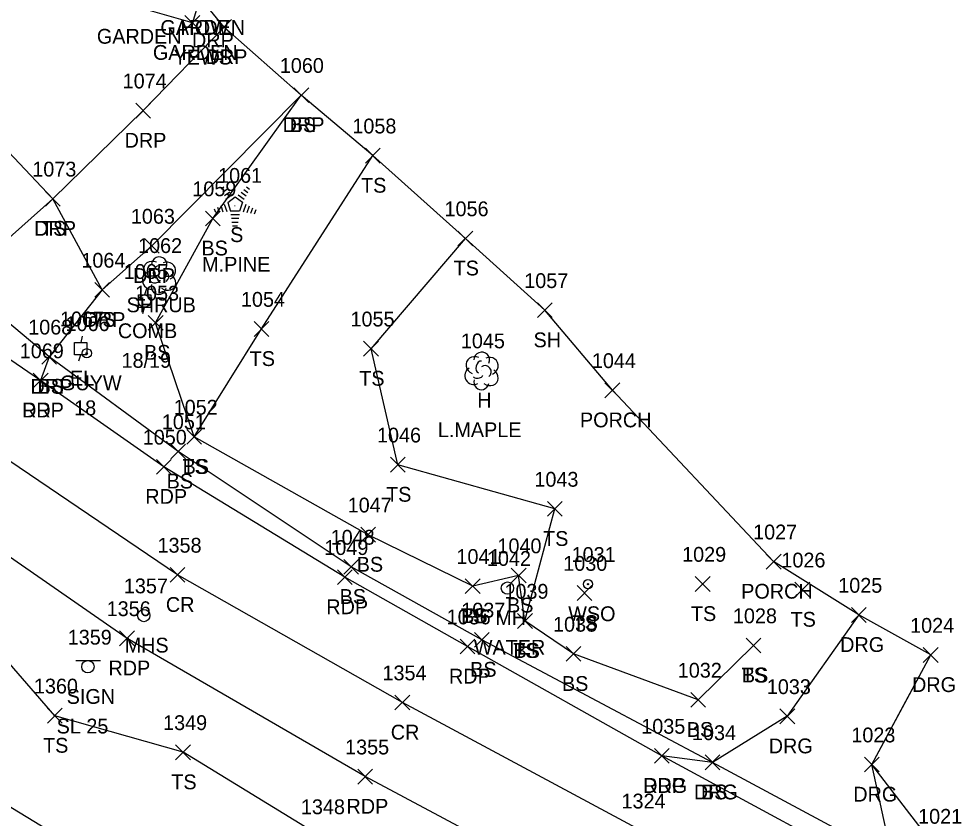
# Model space of a CAD drawing. Extents: x 1461855 to 1464118, y 556196 to 557441.
# Drawn here: x 1462535.4 to 1462662.7, y 556269.9 to 556377.9 of the extents above; entities that cross this region are included whole.
import ezdxf

# ---------------------------------------------------------------- set-up
doc = ezdxf.new("R2010")
doc.units = 0
for name, color, linetype in [('L_A', 7, 'Continuous'), ('L_C', 7, 'Continuous'), ('L_I', 7, 'Continuous'), ('L_TIC', 7, 'Continuous'), ('LAPB', 7, 'Continuous'), ('LBF', 7, 'Continuous'), ('LELB', 7, 'Continuous'), ('LSH', 7, 'Continuous'), ('LSOGP', 7, 'Continuous'), ('LTC', 7, 'Continuous'), ('LTD', 7, 'Continuous'), ('P_A', 7, 'Continuous'), ('P_I', 7, 'Continuous'), ('P_TIC', 7, 'Continuous'), ('PET', 7, 'Continuous'), ('PRC', 7, 'Continuous'), ('R_A', 7, 'Continuous'), ('R_I', 7, 'Continuous'), ('R_TIC', 7, 'Continuous'), ('RDG', 7, 'Continuous'), ('RDP', 7, 'Continuous'), ('S_A', 7, 'Continuous'), ('S_C', 7, 'Continuous'), ('S_I', 7, 'Continuous'), ('SSGN', 7, 'Continuous'), ('U_A', 7, 'Continuous'), ('U_C', 7, 'Continuous'), ('U_I', 7, 'Continuous'), ('UEPT', 7, 'Continuous'), ('UP', 7, 'Continuous'), ('UPGW', 7, 'Continuous'), ('USMH', 7, 'Continuous'), ('UUMH', 7, 'Continuous'), ('UWV', 7, 'Continuous')]:
    doc.layers.add(name, color=color, linetype=linetype)

msp = doc.modelspace()

# ---------------------------------------------------------------- linework, layer by layer
at = {"layer": 'L_TIC'}
for points in [[(1462557.88, 556376.35), (1462559.88, 556378.35)], [(1462559.88, 556376.35), (1462557.88, 556378.35)], [(1462572.59, 556366.59), (1462574.59, 556368.59)], [(1462574.59, 556366.59), (1462572.59, 556368.59)], [(1462582.26, 556358.41), (1462584.26, 556360.41)], [(1462584.26, 556358.41), (1462582.26, 556360.41)], [(1462539.02, 556352.59), (1462541.02, 556354.59)], [(1462541.02, 556352.59), (1462539.02, 556354.59)], [(1462560.65, 556349.93), (1462562.65, 556351.93)], [(1462562.65, 556349.93), (1462560.65, 556351.93)], [(1462594.76, 556347.23), (1462596.76, 556349.23)], [(1462596.76, 556347.23), (1462594.76, 556349.23)], [(1462545.7, 556340.28), (1462547.7, 556342.28)], [(1462547.7, 556340.28), (1462545.7, 556342.28)], [(1462605.48, 556337.53), (1462607.48, 556339.53)], [(1462607.48, 556337.53), (1462605.48, 556339.53)], [(1462552.91, 556335.84), (1462554.91, 556337.84)], [(1462554.91, 556335.84), (1462552.91, 556337.84)], [(1462567.21, 556335), (1462569.21, 556337)], [(1462569.21, 556335), (1462567.21, 556337)], [(1462582.01, 556332.34), (1462584.01, 556334.34)], [(1462584.01, 556332.34), (1462582.01, 556334.34)], [(1462538.52, 556331.25), (1462540.52, 556333.25)], [(1462540.52, 556331.25), (1462538.52, 556333.25)], [(1462614.62, 556326.72), (1462616.62, 556328.72)], [(1462616.62, 556326.72), (1462614.62, 556328.72)], [(1462558.12, 556320.43), (1462560.12, 556322.43)], [(1462560.12, 556320.43), (1462558.12, 556322.43)], [(1462558.12, 556320.43), (1462560.12, 556322.43)], [(1462560.12, 556320.43), (1462558.12, 556322.43)], [(1462555.96, 556318.46), (1462557.96, 556320.46)], [(1462557.96, 556318.46), (1462555.96, 556320.46)], [(1462585.64, 556316.67), (1462587.64, 556318.67)], [(1462587.64, 556316.67), (1462585.64, 556318.67)], [(1462606.85, 556310.7), (1462608.85, 556312.7)], [(1462608.85, 556310.7), (1462606.85, 556312.7)], [(1462581.63, 556307.22), (1462583.63, 556309.22)], [(1462583.63, 556307.22), (1462581.63, 556309.22)], [(1462579.33, 556302.87), (1462581.33, 556304.87)], [(1462581.33, 556302.87), (1462579.33, 556304.87)], [(1462636.4, 556303.58), (1462638.4, 556305.58)], [(1462638.4, 556303.58), (1462636.4, 556305.58)], [(1462601.95, 556301.71), (1462603.95, 556303.71)], [(1462603.95, 556301.71), (1462601.95, 556303.71)], [(1462595.75, 556300.27), (1462597.75, 556302.27)], [(1462597.75, 556300.27), (1462595.75, 556302.27)], [(1462595.75, 556300.27), (1462597.75, 556302.27)], [(1462597.75, 556300.27), (1462595.75, 556302.27)], [(1462626.82, 556300.56), (1462628.82, 556302.56)], [(1462628.82, 556300.56), (1462626.82, 556302.56)], [(1462610.84, 556299.34), (1462612.84, 556301.34)], [(1462612.84, 556299.34), (1462610.84, 556301.34)], [(1462640.28, 556299.79), (1462642.28, 556301.79)], [(1462642.28, 556299.79), (1462640.28, 556301.79)], [(1462602.81, 556295.57), (1462604.81, 556297.57)], [(1462604.81, 556295.57), (1462602.81, 556297.57)], [(1462602.81, 556295.57), (1462604.81, 556297.57)], [(1462604.81, 556295.57), (1462602.81, 556297.57)], [(1462596.97, 556293.03), (1462598.97, 556295.03)], [(1462598.97, 556293.03), (1462596.97, 556295.03)], [(1462633.67, 556292.26), (1462635.67, 556294.26)], [(1462635.67, 556292.26), (1462633.67, 556294.26)], [(1462633.67, 556292.26), (1462635.67, 556294.26)], [(1462635.67, 556292.26), (1462633.67, 556294.26)], [(1462609.37, 556291.12), (1462611.37, 556293.12)], [(1462611.37, 556291.12), (1462609.37, 556293.12)], [(1462626.22, 556284.91), (1462628.22, 556286.91)], [(1462628.22, 556284.91), (1462626.22, 556286.91)], [(1462539.3, 556282.77), (1462541.3, 556284.77)], [(1462541.3, 556282.77), (1462539.3, 556284.77)], [(1462556.62, 556277.83), (1462558.62, 556279.83)], [(1462558.62, 556277.83), (1462556.62, 556279.83)], [(1462628.14, 556276.47), (1462630.14, 556278.47)], [(1462630.14, 556276.47), (1462628.14, 556278.47)]]:
    msp.add_lwpolyline(points, dxfattribs=at)
at = {"layer": 'LAPB'}
msp.add_lwpolyline([(1462559.89, 556380.72), (1462558.88, 556377.35), (1462551.31, 556379.53), (1462545.16, 556389.19), (1462547.91, 556393.8)], dxfattribs=at)
at = {"layer": 'LBF'}
msp.add_lwpolyline([(1462637.4, 556304.58), (1462615.62, 556327.72)], dxfattribs=at)
at = {"layer": 'LELB'}
for points in [[(1462546.7, 556341.28), (1462540.02, 556353.59), (1462515.98, 556379), (1462496.79, 556398.3), (1462485.07, 556421.53), (1462482.02, 556429.93)], [(1462657.04, 556262.88), (1462653.46, 556264.39), (1462629.14, 556277.47), (1462597.97, 556294.03), (1462580.33, 556303.87), (1462556.96, 556319.46), (1462539.52, 556332.25), (1462527.44, 556342.39), (1462506.25, 556364.14), (1462481.42, 556379.06), (1462468.44, 556386.07), (1462453.15, 556402.55), (1462451.23, 556401.93), (1462451.03, 556403.82)], [(1462634.67, 556293.26), (1462627.22, 556285.91), (1462610.37, 556292.12), (1462603.81, 556296.57), (1462602.95, 556302.71), (1462596.75, 556301.27), (1462582.63, 556308.22), (1462559.12, 556321.43), (1462553.91, 556336.84), (1462561.65, 556350.93), (1462573.59, 556367.59)], [(1462559.12, 556321.43), (1462568.21, 556336), (1462583.26, 556359.41)], [(1462599.06, 556233.38), (1462596.16, 556246.32), (1462592.2, 556257.91), (1462576.23, 556267.47), (1462557.62, 556278.83), (1462540.3, 556283.77), (1462528.89, 556296.86), (1462529.08, 556306.21), (1462517.11, 556315.38), (1462502.07, 556325.71), (1462477.93, 556342.63), (1462468.02, 556351.67), (1462460.8, 556357.54)], [(1462566.05, 556253.25), (1462551.07, 556261.22), (1462526.69, 556275.99), (1462519.12, 556289.53), (1462518.52, 556300.62), (1462520.17, 556306.41), (1462512.78, 556309.97), (1462497.67, 556320.06), (1462474.58, 556337.93), (1462471.37, 556338.06), (1462470.04, 556339.66), (1462464.04, 556350.54), (1462457.4, 556355.85)], [(1462603.81, 556296.57), (1462607.85, 556311.7), (1462586.64, 556317.67), (1462583.01, 556333.34), (1462595.76, 556348.23)]]:
    msp.add_lwpolyline(points, dxfattribs=at)
at = {"layer": 'LSH'}
msp.add_line((1462554.36, 556343.26), (1462554.36, 556343.26), dxfattribs=at)
msp.add_line((1462554.36, 556343.26), (1462554.36, 556343.26), dxfattribs=at)
msp.add_arc((1462554.4, 556344.69), 1.05, 335.5272, 180.9563, dxfattribs=at)
for centre, major_axis, ratio, start_param, end_param in [((1462553.56, 556343.93), (1.21, -0.51), 0.895232, 1.570796, 4.712389), ((1462554.15, 556343.72), (-0.208, -0.792), 0.645439, 3.141593, 6.283185), ((1462555.4, 556343.84), (-1.14, -0.48), 0.949671, 1.570796, 4.712389), ((1462553.27, 556342.55), (0.58, -1.04), 0.959034, 3.141593, 6.283185), ((1462554.86, 556343.09), (-0.5, 0.667), 0.989748, 3.141593, 6.283185), ((1462555.36, 556342.43), (-1.09, 0.79), 0.841452, 1.570796, 4.712389), ((1462554.36, 556341.76), (0.26, 1.06), 0.942809, 1.570796, 4.712389), ((1462553.9, 556342.51), (-0.625, -0.083), 0.423636, 0, 3.141593)]:
    msp.add_ellipse(centre, major_axis=major_axis, ratio=ratio, start_param=start_param, end_param=end_param, dxfattribs=at)
at = {"layer": 'LSOGP'}
msp.add_lwpolyline([(1462659.12, 556266.18), (1462650.67, 556277.17), (1462654.65, 556284.57), (1462658.62, 556291.97), (1462648.91, 556297.38), (1462637.4, 556304.58), (1462615.62, 556327.72), (1462606.48, 556338.53), (1462595.76, 556348.23), (1462583.26, 556359.41), (1462573.59, 556367.59), (1462563.17, 556376.78), (1462561.34, 556379.02)], dxfattribs=at)
at = {"layer": 'LTC'}
for p, q in [((1462562.79, 556354.95), (1462563.15, 556355.21)), ((1462563, 556354.48), (1462563.53, 556354.87)), ((1462563.21, 556354.02), (1462563.92, 556354.53)), ((1462565.45, 556354.49), (1462566.13, 556354)), ((1462565.82, 556354.84), (1462566.37, 556354.44)), ((1462566.19, 556355.19), (1462566.61, 556354.88)), ((1462563.42, 556353.55), (1462564.3, 556354.19)), ((1462563.65, 556353.1), (1462564.66, 556353.83)), ((1462564.66, 556353.83), (1462565.66, 556353.11)), ((1462565.08, 556354.14), (1462565.89, 556353.55)), ((1462561.83, 556352.23), (1462561.98, 556351.76)), ((1462562.28, 556352.44), (1462562.49, 556351.79)), ((1462562.74, 556352.66), (1462563.01, 556351.82)), ((1462563.19, 556352.88), (1462563.52, 556351.86)), ((1462563.65, 556353.1), (1462564.03, 556351.9)), ((1462565.26, 556351.9), (1462564.03, 556351.9)), ((1462565.66, 556353.11), (1462565.26, 556351.9)), ((1462566.09, 556352.83), (1462565.75, 556351.79)), ((1462566.54, 556352.58), (1462566.25, 556351.7)), ((1462566.98, 556352.33), (1462566.74, 556351.6)), ((1462567.43, 556352.08), (1462567.24, 556351.51)), ((1462565.23, 556351.4), (1462564.08, 556351.4)), ((1462565.14, 556350.9), (1462564.15, 556350.9)), ((1462565.06, 556350.4), (1462564.23, 556350.4)), ((1462564.97, 556349.9), (1462564.3, 556349.9))]:
    msp.add_line(p, q, dxfattribs=at)
at = {"layer": 'LTD'}
msp.add_line((1462597.92, 556330.39), (1462597.92, 556330.39), dxfattribs=at)
msp.add_line((1462597.92, 556330.39), (1462597.92, 556330.39), dxfattribs=at)
msp.add_arc((1462597.97, 556331.83), 1.05, 335.5272, 180.9563, dxfattribs=at)
for centre, major_axis, ratio, start_param, end_param in [((1462597.13, 556331.06), (1.21, -0.51), 0.895232, 1.570796, 4.712389), ((1462597.72, 556330.85), (-0.208, -0.792), 0.645439, 3.141593, 6.283185), ((1462598.97, 556330.98), (-1.14, -0.48), 0.949671, 1.570796, 4.712389), ((1462596.84, 556329.68), (0.58, -1.04), 0.959034, 3.141593, 6.283185), ((1462598.42, 556330.23), (-0.5, 0.667), 0.989748, 3.141593, 6.283185), ((1462598.92, 556329.56), (-1.09, 0.79), 0.841452, 1.570796, 4.712389), ((1462597.93, 556328.89), (0.26, 1.06), 0.942809, 1.570796, 4.712389), ((1462597.47, 556329.64), (-0.625, -0.083), 0.423636, 0, 3.141593)]:
    msp.add_ellipse(centre, major_axis=major_axis, ratio=ratio, start_param=start_param, end_param=end_param, dxfattribs=at)
at = {"layer": 'P_TIC'}
for points in [[(1462537.38, 556328.05), (1462539.38, 556330.05)], [(1462539.38, 556328.05), (1462537.38, 556330.05)], [(1462554.03, 556316.39), (1462556.03, 556318.39)], [(1462556.03, 556316.39), (1462554.03, 556318.39)], [(1462555.86, 556301.79), (1462557.86, 556303.79)], [(1462557.86, 556301.79), (1462555.86, 556303.79)], [(1462578.48, 556301.48), (1462580.48, 556303.48)], [(1462580.48, 556301.48), (1462578.48, 556303.48)], [(1462549.05, 556293.22), (1462551.05, 556295.22)], [(1462551.05, 556293.22), (1462549.05, 556295.22)], [(1462595.05, 556292.11), (1462597.05, 556294.11)], [(1462597.05, 556292.11), (1462595.05, 556294.11)], [(1462586.25, 556284.55), (1462588.25, 556286.55)], [(1462588.25, 556284.55), (1462586.25, 556286.55)], [(1462621.29, 556277.34), (1462623.29, 556279.34)], [(1462623.29, 556277.34), (1462621.29, 556279.34)], [(1462581.21, 556274.54), (1462583.21, 556276.54)], [(1462583.21, 556274.54), (1462581.21, 556276.54)]]:
    msp.add_lwpolyline(points, dxfattribs=at)
at = {"layer": 'PET'}
for points in [[(1462655.57, 556260.33), (1462622.29, 556278.34), (1462596.05, 556293.11), (1462579.48, 556302.48), (1462555.03, 556317.39), (1462538.38, 556329.05), (1462522.59, 556339.78), (1462499.49, 556355.96), (1462479.91, 556370.2), (1462462.39, 556383.08), (1462450, 556394.49), (1462423.07, 556412.09), (1462414.08, 556417.65), (1462394.93, 556425.92), (1462382.48, 556434.45), (1462359.05, 556435.71), (1462354.93, 556436.4), (1462348.34, 556437.43), (1462333.33, 556438.52), (1462332.9, 556427.26)], [(1462646.26, 556240.88), (1462638.39, 556245.28), (1462613.44, 556258.88), (1462582.21, 556275.54), (1462550.05, 556294.22), (1462512.2, 556320.44), (1462479.05, 556344.07), (1462460.8, 556357.54), (1462433.62, 556376.17), (1462410.33, 556391.48), (1462383.13, 556406.1), (1462371.43, 556410.47), (1462364.34, 556412.93), (1462357.61, 556414.67), (1462347.76, 556416.01), (1462332.39, 556416.61), (1462332.9, 556427.26)]]:
    msp.add_lwpolyline(points, dxfattribs=at)
at = {"layer": 'PRC'}
msp.add_lwpolyline([(1462651.54, 556250.53), (1462619.54, 556268.24), (1462587.25, 556285.55), (1462556.86, 556302.79), (1462518.1, 556329.05), (1462484.17, 556354), (1462438.09, 556386.5), (1462416.23, 556401.26), (1462387.08, 556415.75), (1462366.36, 556422.8), (1462356.92, 556424.51), (1462339.71, 556426.54), (1462332.9, 556427.26)], dxfattribs=at)
at = {"layer": 'R_TIC'}
for points in [[(1462562.17, 556375.78), (1462564.17, 556377.78)], [(1462564.17, 556375.78), (1462562.17, 556377.78)], [(1462572.59, 556366.59), (1462574.59, 556368.59)], [(1462574.59, 556366.59), (1462572.59, 556368.59)], [(1462551.23, 556364.49), (1462553.23, 556366.49)], [(1462553.23, 556364.49), (1462551.23, 556366.49)], [(1462539.02, 556352.59), (1462541.02, 556354.59)], [(1462541.02, 556352.59), (1462539.02, 556354.59)], [(1462552.39, 556346.22), (1462554.39, 556348.22)], [(1462554.39, 556346.22), (1462552.39, 556348.22)], [(1462545.7, 556340.28), (1462547.7, 556342.28)], [(1462547.7, 556340.28), (1462545.7, 556342.28)], [(1462538.52, 556331.25), (1462540.52, 556333.25)], [(1462540.52, 556331.25), (1462538.52, 556333.25)], [(1462537.38, 556328.05), (1462539.38, 556330.05)], [(1462539.38, 556328.05), (1462537.38, 556330.05)], [(1462647.91, 556296.38), (1462649.91, 556298.38)], [(1462649.91, 556296.38), (1462647.91, 556298.38)], [(1462657.62, 556290.97), (1462659.62, 556292.97)], [(1462659.62, 556290.97), (1462657.62, 556292.97)], [(1462638.25, 556282.69), (1462640.25, 556284.69)], [(1462640.25, 556282.69), (1462638.25, 556284.69)], [(1462621.29, 556277.34), (1462623.29, 556279.34)], [(1462623.29, 556277.34), (1462621.29, 556279.34)], [(1462628.14, 556276.47), (1462630.14, 556278.47)], [(1462630.14, 556276.47), (1462628.14, 556278.47)], [(1462649.67, 556276.17), (1462651.67, 556278.17)], [(1462651.67, 556276.17), (1462649.67, 556278.17)]]:
    msp.add_lwpolyline(points, dxfattribs=at)
at = {"layer": 'RDG'}
for points in [[(1462648.91, 556297.38), (1462639.25, 556283.69), (1462629.14, 556277.47), (1462622.29, 556278.34)], [(1462655.57, 556260.33), (1462653.46, 556264.39), (1462650.67, 556277.17), (1462658.62, 556291.97)]]:
    msp.add_lwpolyline(points, dxfattribs=at)
at = {"layer": 'RDP'}
for points in [[(1462522.59, 556339.78), (1462527.44, 556342.39), (1462540.02, 556353.59), (1462552.23, 556365.49), (1462563.17, 556376.78), (1462561.34, 556379.02)], [(1462573.59, 556367.59), (1462553.39, 556347.22), (1462546.7, 556341.28), (1462539.52, 556332.25), (1462538.38, 556329.05)]]:
    msp.add_lwpolyline(points, dxfattribs=at)
at = {"layer": 'SSGN'}
for p, q in [((1462543.12, 556291.23), (1462546.45, 556291.23)), ((1462544.76, 556290.39), (1462544.76, 556290.39))]:
    msp.add_line(p, q, dxfattribs=at)
msp.add_circle((1462544.76, 556290.39), 0.833, dxfattribs=at)
at = {"layer": 'UEPT'}
for p, q in [((1462542.97, 556332.51), (1462542.97, 556334.18)), ((1462542.97, 556334.18), (1462544.64, 556334.18)), ((1462543.97, 556335.01), (1462543.81, 556334.18)), ((1462544.64, 556334.18), (1462544.64, 556332.51)), ((1462543.81, 556333.35), (1462543.81, 556333.35)), ((1462544.64, 556332.51), (1462542.97, 556332.51)), ((1462543.56, 556331.68), (1462543.81, 556332.51))]:
    msp.add_line(p, q, dxfattribs=at)
at = {"layer": 'UP'}
for p, q in [((1462551.59, 556338.92), (1462551.59, 556340.59)), ((1462551.59, 556340.59), (1462553.25, 556340.59)), ((1462552.67, 556341.42), (1462552.42, 556340.59)), ((1462553.25, 556340.59), (1462553.25, 556338.92)), ((1462552.42, 556339.76), (1462552.42, 556339.76)), ((1462553.25, 556338.92), (1462551.59, 556338.92)), ((1462552.17, 556338.09), (1462552.42, 556338.92))]:
    msp.add_line(p, q, dxfattribs=at)
msp.add_circle((1462552.42, 556339.76), 0.833, dxfattribs=at)
at = {"layer": 'UPGW'}
for radius in [0.625, 0.0833]:
    msp.add_circle((1462544.61, 556332.72), radius, dxfattribs=at)
at = {"layer": 'USMH'}
for p, q in [((1462552.31, 556297.3), (1462552.31, 556297.3)), ((1462553.14, 556297.3), (1462553.14, 556297.3))]:
    msp.add_line(p, q, dxfattribs=at)
msp.add_circle((1462552.31, 556297.3), 0.833, dxfattribs=at)
at = {"layer": 'UUMH'}
for p, q in [((1462601.44, 556301.01), (1462601.44, 556301.01)), ((1462602.27, 556301.01), (1462602.27, 556301.01))]:
    msp.add_line(p, q, dxfattribs=at)
msp.add_circle((1462601.44, 556301.01), 0.833, dxfattribs=at)
at = {"layer": 'UWV'}
for radius in [0.625, 0.0833]:
    msp.add_circle((1462612.32, 556301.54), radius, dxfattribs=at)

# ---------------------------------------------------------------- texts
at = {"layer": 'L_A'}
for s, p in [('GARDEN', (1462554.56, 556375.72)), ('HOW', (1462557.27, 556375.72)), ('GARDEN', (1462545.98, 556374.53)), ('GARDEN', (1462553.55, 556372.35)), ('BS', (1462572.03, 556362.59)), ('TS', (1462581.67, 556354.41)), ('TS', (1462538.43, 556348.59)), ('S', (1462563.98, 556347.74)), ('BS', (1462560.1, 556345.93)), ('TS', (1462594.17, 556343.23)), ('SHRUB', (1462549.99, 556338.26)), ('TS', (1462545.1, 556336.28)), ('SH', (1462604.97, 556333.53)), ('BS', (1462552.35, 556331.84)), ('TS', (1462566.62, 556331)), ('TS', (1462581.42, 556328.34)), ('BS', (1462537.96, 556327.25)), ('H', (1462597.36, 556325.39)), ('PORCH', (1462611.24, 556322.72)), ('TS', (1462557.53, 556316.43)), ('BS', (1462557.56, 556316.43)), ('BS', (1462555.4, 556314.46)), ('TS', (1462585.05, 556312.67)), ('TS', (1462606.26, 556306.7)), ('BS', (1462581.08, 556303.22)), ('PORCH', (1462633.02, 556299.58)), ('BS', (1462578.77, 556298.87)), ('BS', (1462601.39, 556297.71)), ('TS', (1462626.23, 556296.56)), ('TS', (1462595.16, 556296.27)), ('BS', (1462595.19, 556296.27)), ('TS', (1462610.25, 556295.34)), ('TS', (1462639.69, 556295.79)), ('TS', (1462602.22, 556291.57)), ('BS', (1462602.25, 556291.57)), ('BS', (1462596.41, 556289.03)), ('TS', (1462633.08, 556288.26)), ('BS', (1462633.11, 556288.26)), ('BS', (1462608.81, 556287.12)), ('BS', (1462625.66, 556280.91)), ('TS', (1462538.71, 556278.77)), ('TS', (1462556.03, 556273.83)), ('BS', (1462627.58, 556272.47))]:
    msp.add_text(s, height=2, dxfattribs=at).set_placement(p)
at = {"layer": 'L_C'}
for s, p in [('YEWS', (1462556.34, 556371.72)), ('M.PINE', (1462560.2, 556343.74)), ('L.MAPLE', (1462592.04, 556321.39))]:
    msp.add_text(s, height=2, dxfattribs=at).set_placement(p)
at = {"layer": 'L_I'}
for s, p in [('1060', (1462570.69, 556370.59)), ('1058', (1462580.49, 556362.41)), ('1073', (1462537.25, 556356.59)), ('1061', (1462562.35, 556355.74)), ('1059', (1462558.87, 556353.93)), ('1056', (1462592.94, 556351.23)), ('1062', (1462551.54, 556346.26)), ('1064', (1462543.88, 556344.28)), ('1057', (1462603.71, 556341.53)), ('1053', (1462551.13, 556339.84)), ('1054', (1462565.44, 556339)), ('1055', (1462580.24, 556336.34)), ('1068', (1462536.7, 556335.25)), ('1045', (1462595.15, 556333.39)), ('1044', (1462612.85, 556330.72)), ('1052', (1462556.35, 556324.43)), ('1052', (1462556.35, 556324.43)), ('1051', (1462554.75, 556322.46)), ('1046', (1462583.82, 556320.67)), ('1043', (1462605.08, 556314.7)), ('1047', (1462579.86, 556311.22)), ('1048', (1462577.56, 556306.87)), ('1027', (1462634.63, 556307.58)), ('1040', (1462600.09, 556305.71)), ('1041', (1462594.55, 556304.27)), ('1041', (1462594.55, 556304.27)), ('1029', (1462625.04, 556304.56)), ('1030', (1462608.98, 556303.34)), ('1026', (1462638.45, 556303.79)), ('1039', (1462601.03, 556299.57)), ('1039', (1462601.03, 556299.57)), ('1037', (1462595.2, 556297.03)), ('1038', (1462607.6, 556295.12)), ('1028', (1462631.9, 556296.26)), ('1028', (1462631.9, 556296.26)), ('1032', (1462624.45, 556288.91)), ('1360', (1462537.47, 556286.77)), ('1349', (1462554.92, 556281.83)), ('1034', (1462626.37, 556280.47)), ('1348', (1462573.54, 556270.47))]:
    msp.add_text(s, height=2, dxfattribs=at).set_placement(p)
at = {"layer": 'LTC'}
msp.add_text('.', height=1.04, rotation=270, dxfattribs=at).set_placement((1462564.54, 556352.84))
at = {"layer": 'P_A'}
for s, p in [('RDP', (1462535.87, 556324.05)), ('RDP', (1462552.52, 556312.39)), ('CR', (1462555.3, 556297.79)), ('RDP', (1462576.97, 556297.48)), ('RDP', (1462547.54, 556289.22)), ('RDP', (1462593.54, 556288.11)), ('CR', (1462585.68, 556280.55)), ('RDP', (1462619.78, 556273.34)), ('RDP', (1462579.7, 556270.54))]:
    msp.add_text(s, height=2, dxfattribs=at).set_placement(p)
at = {"layer": 'P_I'}
for s, p in [('1069', (1462535.56, 556332.05)), ('1050', (1462552.17, 556320.39)), ('1358', (1462554.17, 556305.79)), ('1049', (1462576.7, 556305.48)), ('1356', (1462547.3, 556297.22)), ('1036', (1462593.23, 556296.11)), ('1354', (1462584.56, 556288.55)), ('1035', (1462619.52, 556281.34)), ('1355', (1462579.51, 556278.54)), ('1324', (1462616.85, 556271.24))]:
    msp.add_text(s, height=2, dxfattribs=at).set_placement(p)
at = {"layer": 'R_A'}
for s, p in [('DRP', (1462558.83, 556374.02)), ('DRP', (1462560.66, 556371.78)), ('DRP', (1462571.08, 556362.59)), ('DRP', (1462549.72, 556360.49)), ('DRP', (1462537.51, 556348.59)), ('DRP', (1462550.88, 556342.22)), ('DRP', (1462544.18, 556336.28)), ('DRP', (1462537.01, 556327.25)), ('DRP', (1462535.87, 556324.05)), ('DRG', (1462646.39, 556292.38)), ('DRG', (1462656.1, 556286.97)), ('DRG', (1462636.74, 556278.69)), ('DRG', (1462619.78, 556273.34)), ('DRG', (1462626.63, 556272.47)), ('DRG', (1462648.16, 556272.17))]:
    msp.add_text(s, height=2, dxfattribs=at).set_placement(p)
at = {"layer": 'R_I'}
for s, p in [('1060', (1462570.69, 556370.59)), ('1074', (1462549.46, 556368.49)), ('1073', (1462537.25, 556356.59)), ('1063', (1462550.57, 556350.22)), ('1064', (1462543.88, 556344.28)), ('1068', (1462536.7, 556335.25)), ('1069', (1462535.56, 556332.05)), ('1025', (1462646.13, 556300.38)), ('1024', (1462655.84, 556294.97)), ('1033', (1462636.48, 556286.69)), ('1035', (1462619.52, 556281.34)), ('1034', (1462626.37, 556280.47)), ('1023', (1462647.9, 556280.17))]:
    msp.add_text(s, height=2, dxfattribs=at).set_placement(p)
at = {"layer": 'S_A'}
msp.add_text('SIGN', height=2, dxfattribs=at).set_placement((1462541.9, 556285.37))
at = {"layer": 'S_C'}
msp.add_text('SL 25', height=2, dxfattribs=at).set_placement((1462540.54, 556281.37))
at = {"layer": 'S_I'}
msp.add_text('1359', height=2, dxfattribs=at).set_placement((1462542.04, 556293.37))
at = {"layer": 'U_A'}
for s, p in [('COMB', (1462548.81, 556334.76)), ('EL', (1462542.34, 556328.35)), ('GUYW', (1462541, 556327.72)), ('WSO', (1462609.65, 556296.54)), ('MH', (1462599.8, 556296.01)), ('MHS', (1462549.73, 556292.3))]:
    msp.add_text(s, height=2, dxfattribs=at).set_placement(p)
at = {"layer": 'U_C'}
for s, p in [('18/19', (1462549.31, 556330.76)), ('18', (1462542.91, 556324.35)), ('WATER', (1462596.9, 556292.01))]:
    msp.add_text(s, height=2, dxfattribs=at).set_placement(p)
at = {"layer": 'U_I'}
for s, p in [('1065', (1462549.6, 556342.76)), ('1067', (1462540.99, 556336.35)), ('1066', (1462541.74, 556335.72)), ('1042', (1462598.67, 556304.01)), ('1031', (1462610.11, 556304.54)), ('1357', (1462549.62, 556300.3)), ('1021', (1462656.92, 556269.18))]:
    msp.add_text(s, height=2, dxfattribs=at).set_placement(p)

doc.saveas('drawing.dxf')
